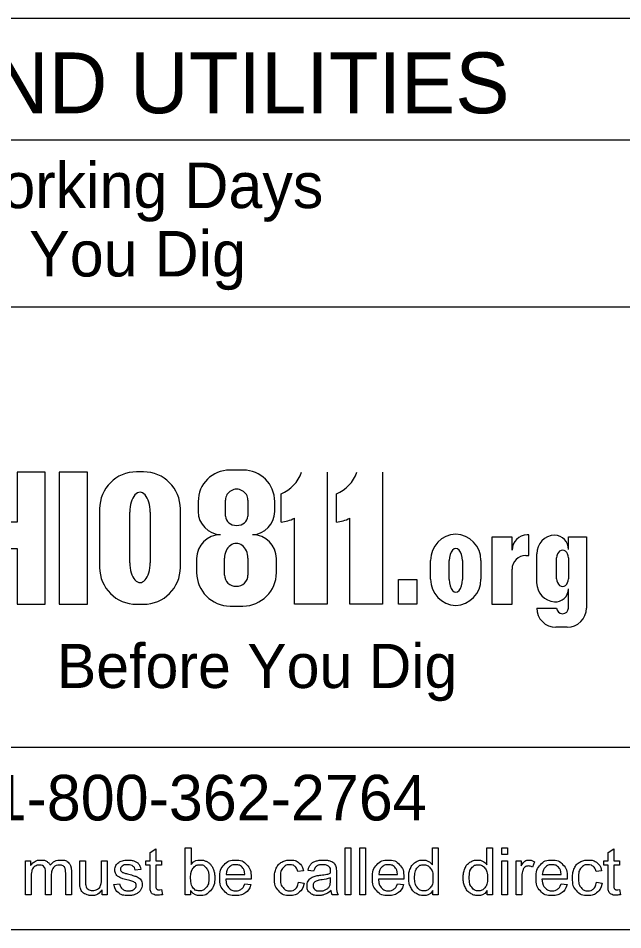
# Model space of a CAD drawing. Extents: x 0 to 34, y 0 to 22.
# Drawn here: x 5.246 to 7.234, y 2.235 to 5.235 of the extents above; entities that cross this region are included whole.
import ezdxf

# ---------------------------------------------------------------- set-up
doc = ezdxf.new("R2010")
doc.units = 0
doc.layers.add('SH_Data', color=7, linetype='Continuous')

msp = doc.modelspace()

# ---------------------------------------------------------------- linework, layer by layer
at = {"layer": 'SH_Data'}
for p, q in [((3.2423, 5.2348), (7.9923, 5.2348)), ((3.2423, 4.8348), (7.9923, 4.8348)), ((3.2423, 4.2848), (7.9923, 4.2848)), ((5.6572, 3.7418), (5.6347, 3.7418)), ((5.9855, 3.7477), (5.941, 3.7477)), ((6.2616, 3.7405), (6.2616, 3.3059)), ((6.4435, 3.7405), (6.4435, 3.3059)), ((6.11, 3.5766), (6.11, 3.6691)), ((6.292, 3.5766), (6.292, 3.6691)), ((5.8374, 3.6441), (5.8374, 3.6111)), ((5.9273, 3.5957), (5.9273, 3.649)), ((6.0008, 3.649), (6.0008, 3.5957)), ((6.0891, 3.6111), (6.0891, 3.6441)), ((5.5132, 3.6203), (5.5132, 3.4274)), ((5.6122, 3.4429), (5.6122, 3.6091)), ((5.6799, 3.6091), (5.6799, 3.4429)), ((5.7787, 3.4274), (5.7787, 3.6203)), ((6.1539, 3.3059), (6.1539, 3.5893)), ((6.3359, 3.3059), (6.3359, 3.5893)), ((6.8696, 3.5273), (6.8033, 3.5273)), ((6.8033, 3.5273), (6.8033, 3.3059)), ((6.8696, 3.4844), (6.8696, 3.5273)), ((6.9249, 3.5343), (6.9195, 3.5343)), ((6.9249, 3.4665), (6.9249, 3.5343)), ((7.055, 3.4864), (7.055, 3.5285)), ((7.055, 3.5285), (7.1142, 3.5285)), ((7.1142, 3.5285), (7.1142, 3.2937)), ((5.8324, 3.4565), (5.8324, 3.4102)), ((5.924, 3.4022), (5.924, 3.4577)), ((6.0012, 3.4577), (6.0012, 3.4022)), ((6.0946, 3.4102), (6.0946, 3.4565)), ((6.6015, 3.3886), (6.6015, 3.4502)), ((6.6626, 3.3875), (6.6626, 3.4502)), ((6.7063, 3.4502), (6.7063, 3.3875)), ((6.7674, 3.4502), (6.7674, 3.3886)), ((6.9144, 3.4665), (6.9249, 3.4665)), ((6.9506, 3.3771), (6.9506, 3.4717)), ((7.0162, 3.3898), (7.0162, 3.4591)), ((7.055, 3.4591), (7.055, 3.3898)), ((6.8696, 3.3059), (6.8696, 3.4217)), ((7.055, 3.2937), (7.055, 3.3567)), ((5.6347, 3.3059), (5.6572, 3.3059)), ((5.9423, 3.3003), (5.9847, 3.3003)), ((6.2616, 3.3059), (6.1539, 3.3059)), ((6.4435, 3.3059), (6.3359, 3.3059)), ((6.8033, 3.3059), (6.8696, 3.3059)), ((6.9506, 3.2937), (7.0162, 3.2937)), ((7.0507, 3.2302), (7.0141, 3.2302)), ((7.9923, 2.8348), (3.2423, 2.8348)), ((7.9923, 2.2348), (3.2423, 2.2348))]:
    msp.add_line(p, q, dxfattribs=at)
for points in [[(5.1728, 3.4897), (5.242, 3.4897), (5.242, 3.3059), (5.3343, 3.3059), (5.3343, 3.7405), (5.242, 3.7405), (5.242, 3.5766), (5.1728, 3.5766), (5.1728, 3.7405)], [(5.3804, 3.3059), (5.4738, 3.3059), (5.4738, 3.7405), (5.3804, 3.7405), (5.3804, 3.3059)], [(5.911, 3.5351), (5.911, 3.5351)], [(6.016, 3.5351), (6.016, 3.5351)], [(5.6791, 2.3828), (5.6791, 2.4471), (5.6651, 2.4471), (5.6651, 2.4618), (5.6791, 2.4618), (5.6791, 2.4894), (5.698, 2.5007), (5.698, 2.4618), (5.7169, 2.4618), (5.7169, 2.4471), (5.698, 2.4471), (5.698, 2.3817)], [(5.8125, 2.3501), (5.795, 2.3501), (5.795, 2.5041), (5.8139, 2.5041), (5.8139, 2.4493)], [(6.3209, 2.3501), (6.3209, 2.5041), (6.3398, 2.5041), (6.3398, 2.3501), (6.3209, 2.3501)], [(6.3687, 2.3501), (6.3687, 2.5041), (6.3876, 2.5041), (6.3876, 2.3501), (6.3687, 2.3501)], [(6.6075, 2.4489), (6.6075, 2.5041), (6.6264, 2.5041), (6.6264, 2.3501), (6.6089, 2.3501)], [(6.7869, 2.4489), (6.7869, 2.5041), (6.8058, 2.5041), (6.8058, 2.3501), (6.7883, 2.3501)], [(6.8356, 2.4824), (6.8356, 2.5041), (6.8545, 2.5041), (6.8545, 2.4824), (6.8356, 2.4824)], [(7.1855, 2.3828), (7.1855, 2.4471), (7.1715, 2.4471), (7.1715, 2.4618), (7.1855, 2.4618), (7.1855, 2.4894), (7.2044, 2.5007), (7.2044, 2.4618), (7.2233, 2.4618), (7.2233, 2.4471), (7.2044, 2.4471), (7.2044, 2.3817)], [(5.2692, 2.3501), (5.2692, 2.4618), (5.2861, 2.4618), (5.2861, 2.446)], [(5.4479, 2.3926), (5.4479, 2.4618), (5.4668, 2.4618), (5.4668, 2.3999)], [(5.5194, 2.402), (5.5194, 2.4618), (5.5383, 2.4618), (5.5383, 2.3501), (5.5214, 2.3501)], [(6.8356, 2.3501), (6.8356, 2.4618), (6.8545, 2.4618), (6.8545, 2.3501), (6.8356, 2.3501)], [(6.883, 2.3501), (6.883, 2.4618), (6.9, 2.4618), (6.9, 2.4449)], [(5.649, 2.4329), (5.6305, 2.4304)], [(6.9436, 2.4582), (6.9369, 2.4407)], [(5.2881, 2.408), (5.2881, 2.3501), (5.2692, 2.3501)], [(5.3544, 2.4149), (5.3544, 2.3501), (5.3355, 2.3501), (5.3355, 2.4226)], [(5.4205, 2.4267), (5.4205, 2.3501), (5.4016, 2.3501), (5.4016, 2.4204)], [(6.0111, 2.4011), (5.9279, 2.4011)], [(5.929, 2.4166), (5.9913, 2.4166)], [(6.1838, 2.4289), (6.1654, 2.4261)], [(6.2171, 2.4274), (6.1986, 2.4298)], [(6.2729, 2.3992), (6.273, 2.4061)], [(6.292, 2.4221), (6.292, 2.3969)], [(6.5133, 2.4011), (6.43, 2.4011)], [(6.4311, 2.4166), (6.4934, 2.4166)], [(6.9019, 2.4086), (6.9019, 2.3501), (6.883, 2.3501)], [(7.0512, 2.4011), (6.968, 2.4011)], [(6.969, 2.4166), (7.0314, 2.4166)], [(7.1641, 2.4289), (7.1457, 2.4261)], [(5.5604, 2.3835), (5.5791, 2.3864)], [(5.9911, 2.3862), (6.0106, 2.3837)], [(6.167, 2.391), (6.1855, 2.3885)], [(6.4932, 2.3862), (6.5127, 2.3837)], [(7.0312, 2.3862), (7.0507, 2.3837)], [(7.1473, 2.391), (7.1659, 2.3885)], [(5.5214, 2.3501), (5.5214, 2.3666)], [(5.7169, 2.367), (5.7196, 2.3503)], [(5.8125, 2.3641), (5.8125, 2.3501)], [(6.298, 2.3501), (6.2783, 2.3501)], [(6.6089, 2.3501), (6.6089, 2.3642)], [(6.7883, 2.3501), (6.7883, 2.3642)], [(7.2233, 2.367), (7.226, 2.3503)]]:
    msp.add_lwpolyline(points, dxfattribs=at)
msp.add_lwpolyline([(6.4963, 3.3875), (6.5562, 3.3875), (6.5562, 3.3059), (6.4963, 3.3059)], close=True, dxfattribs=at)
for centre, radius, start, end in [((5.6347, 3.6203), 0.1215, 90, 180), ((5.6572, 3.6203), 0.1215, 0, 90), ((5.941, 3.6441), 0.1036, 90, 180), ((5.9855, 3.6441), 0.1036, 0, 90), ((6.064, 3.7801), 0.1202, 292.5572, 340.7355), ((6.2459, 3.7801), 0.1202, 292.5572, 340.7355), ((5.9135, 3.6111), 0.076, 180, 268.1442), ((6.0131, 3.6111), 0.076, 272.2058, 0), ((6.0992, 3.6962), 0.1202, 275.1733, 297.0931), ((6.2811, 3.6962), 0.1202, 275.1733, 297.0931), ((5.911, 3.4565), 0.0786, 90, 180), ((6.016, 3.4565), 0.0786, 0, 90), ((6.6884, 3.4502), 0.0869, 92.5886, 180), ((6.6805, 3.4502), 0.0869, 0, 87.4114), ((6.9195, 3.4844), 0.0498, 90, 180), ((7.0129, 3.4717), 0.0623, 92.6865, 180), ((7.0074, 3.4864), 0.0476, 0, 86.9262), ((6.9144, 3.4217), 0.0448, 90, 180), ((5.6347, 3.4274), 0.1215, 180, 270), ((5.6572, 3.4274), 0.1215, 270, 0), ((5.9423, 3.4102), 0.1099, 180, 270), ((5.9847, 3.4102), 0.1099, 270, 0), ((6.6884, 3.3886), 0.0869, 180, 267.4114), ((6.6805, 3.3886), 0.0869, 272.5886, 0), ((7.0134, 3.3771), 0.0629, 180, 265.7132), ((7.0126, 3.3567), 0.0424, 264.7825, 0), ((7.0141, 3.2937), 0.0635, 180, 270), ((7.0507, 3.2937), 0.0635, 270, 0)]:
    msp.add_arc(centre, radius, start, end, dxfattribs=at)
for centre, major_axis, ratio, start_param, end_param in [((5.6461, 3.6091), (0, 0.0657), 0.514403, 4.712389, 7.853982), ((5.964, 3.649), (0.0368, 0), 0.969373, 0, 3.141593), ((5.964, 3.5957), (0.0368, 0), 0.818453, 3.141593, 6.283185), ((5.9626, 3.4577), (0, 0.0486), 0.794529, 4.712389, 7.853982), ((6.6845, 3.4502), (0, 0.0395), 0.553236, 4.712389, 7.853982), ((7.0356, 3.4591), (0, 0.025), 0.777179, 4.712389, 7.853982), ((5.6461, 3.4429), (0, 0.0657), 0.514403, 1.570796, 4.712389), ((5.9626, 3.4022), (0.0386, 0), 0.959837, 3.141593, 6.283185), ((6.6845, 3.3875), (0, 0.0419), 0.522014, 1.570796, 4.712389), ((7.0356, 3.3898), (0, 0.025), 0.777179, 1.570796, 4.712389), ((7.0356, 3.2937), (0.0194, 0), 0.959012, 3.141593, 6.283185)]:
    msp.add_ellipse(centre, major_axis=major_axis, ratio=ratio, start_param=start_param, end_param=end_param, dxfattribs=at)
for points, degree in [([(5.2861, 2.446), (5.2913, 2.4542), (5.3, 2.4592), (5.3088, 2.4642), (5.3199, 2.4642), (5.3323, 2.4642), (5.3402, 2.4591), (5.3482, 2.4539), (5.3514, 2.4446), (5.3647, 2.4642), (5.3859, 2.4642), (5.4026, 2.4642), (5.4115, 2.455), (5.4205, 2.4458), (5.4205, 2.4267)], 3), ([(5.5791, 2.3864), (5.5806, 2.3752), (5.5879, 2.3692), (5.5951, 2.3632), (5.608, 2.3632), (5.6211, 2.3632), (5.6274, 2.3685), (5.6337, 2.3738), (5.6337, 2.381), (5.6337, 2.3874), (5.6282, 2.3911), (5.6243, 2.3936), (5.6088, 2.3975), (5.588, 2.4027), (5.5799, 2.4066), (5.5719, 2.4104), (5.5677, 2.4172), (5.5636, 2.4239), (5.5636, 2.4321), (5.5636, 2.4396), (5.567, 2.4459), (5.5704, 2.4523), (5.5763, 2.4565), (5.5807, 2.4597), (5.5883, 2.462), (5.596, 2.4642), (5.6047, 2.4642), (5.6179, 2.4642), (5.6278, 2.4604), (5.6377, 2.4567), (5.6425, 2.4502), (5.6472, 2.4437), (5.649, 2.4329)], 3), ([(5.8139, 2.4493), (5.8259, 2.4642), (5.8445, 2.4642), (5.8548, 2.4642), (5.864, 2.4601), (5.8732, 2.4559), (5.8791, 2.4484), (5.885, 2.4409), (5.8884, 2.4303), (5.8917, 2.4197), (5.8917, 2.4076), (5.8917, 2.379), (5.8776, 2.3633), (5.8634, 2.3477), (5.8435, 2.3477), (5.8238, 2.3477), (5.8125, 2.3641)], 3), ([(6.0106, 2.3837), (6.006, 2.3666), (5.9935, 2.3571), (5.981, 2.3477), (5.9616, 2.3477), (5.9371, 2.3477), (5.9228, 2.3627), (5.9084, 2.3778), (5.9084, 2.405), (5.9084, 2.4332), (5.9229, 2.4487), (5.9374, 2.4642), (5.9605, 2.4642), (5.9829, 2.4642), (5.9971, 2.449), (6.0112, 2.4338), (6.0112, 2.4061), (6.0112, 2.4044), (6.0111, 2.4011)], 3), ([(6.1855, 2.3885), (6.1825, 2.3694), (6.1699, 2.3585), (6.1574, 2.3477), (6.1391, 2.3477), (6.1162, 2.3477), (6.1023, 2.3626), (6.0884, 2.3776), (6.0884, 2.4055), (6.0884, 2.4236), (6.0943, 2.4371), (6.1003, 2.4507), (6.1126, 2.4575), (6.1248, 2.4642), (6.1392, 2.4642), (6.1574, 2.4642), (6.169, 2.455), (6.1805, 2.4458), (6.1838, 2.4289)], 3), ([(6.1986, 2.4298), (6.2011, 2.4417), (6.2069, 2.449), (6.2126, 2.4563), (6.2236, 2.4603), (6.2345, 2.4642), (6.2489, 2.4642), (6.2631, 2.4642), (6.2721, 2.4609), (6.281, 2.4575), (6.2852, 2.4524), (6.2894, 2.4473), (6.2911, 2.4395), (6.292, 2.4347), (6.292, 2.4221)], 3), ([(6.5127, 2.3837), (6.5081, 2.3666), (6.4956, 2.3571), (6.4831, 2.3477), (6.4637, 2.3477), (6.4392, 2.3477), (6.4249, 2.3627), (6.4106, 2.3778), (6.4106, 2.405), (6.4106, 2.4332), (6.4251, 2.4487), (6.4395, 2.4642), (6.4627, 2.4642), (6.485, 2.4642), (6.4992, 2.449), (6.5134, 2.4338), (6.5134, 2.4061), (6.5134, 2.4044), (6.5133, 2.4011)], 3), ([(6.6089, 2.3642), (6.5983, 2.3477), (6.5777, 2.3477), (6.5644, 2.3477), (6.5532, 2.355), (6.542, 2.3624), (6.5358, 2.3756), (6.5297, 2.3887), (6.5297, 2.4058), (6.5297, 2.4225), (6.5353, 2.4361), (6.5408, 2.4497), (6.5519, 2.457), (6.563, 2.4642), (6.5768, 2.4642), (6.5869, 2.4642), (6.5947, 2.46), (6.6026, 2.4557), (6.6075, 2.4489)], 3), ([(6.7883, 2.3642), (6.7777, 2.3477), (6.7571, 2.3477), (6.7437, 2.3477), (6.7325, 2.355), (6.7213, 2.3624), (6.7152, 2.3756), (6.709, 2.3887), (6.709, 2.4058), (6.709, 2.4225), (6.7146, 2.4361), (6.7202, 2.4497), (6.7313, 2.457), (6.7424, 2.4642), (6.7561, 2.4642), (6.7662, 2.4642), (6.7741, 2.46), (6.7819, 2.4557), (6.7869, 2.4489)], 3), ([(6.9, 2.4449), (6.9065, 2.4567), (6.912, 2.4605), (6.9175, 2.4642), (6.9242, 2.4642), (6.9337, 2.4642), (6.9436, 2.4582)], 3), ([(7.0507, 2.3837), (7.0461, 2.3666), (7.0336, 2.3571), (7.0211, 2.3477), (7.0016, 2.3477), (6.9772, 2.3477), (6.9628, 2.3627), (6.9485, 2.3778), (6.9485, 2.405), (6.9485, 2.4332), (6.963, 2.4487), (6.9775, 2.4642), (7.0006, 2.4642), (7.023, 2.4642), (7.0371, 2.449), (7.0513, 2.4338), (7.0513, 2.4061), (7.0513, 2.4044), (7.0512, 2.4011)], 3), ([(7.1659, 2.3885), (7.1628, 2.3694), (7.1503, 2.3585), (7.1377, 2.3477), (7.1194, 2.3477), (7.0965, 2.3477), (7.0826, 2.3626), (7.0687, 2.3776), (7.0687, 2.4055), (7.0687, 2.4236), (7.0747, 2.4371), (7.0807, 2.4507), (7.0929, 2.4575), (7.1052, 2.4642), (7.1196, 2.4642), (7.1377, 2.4642), (7.1493, 2.455), (7.1609, 2.4458), (7.1641, 2.4289)], 3), ([(5.3355, 2.4226), (5.3355, 2.4352), (5.3308, 2.4415), (5.3262, 2.4478), (5.3157, 2.4478), (5.3077, 2.4478), (5.3009, 2.4436), (5.2941, 2.4394), (5.2911, 2.4313), (5.2881, 2.4232), (5.2881, 2.408)], 3), ([(5.4016, 2.4204), (5.4016, 2.4317), (5.3997, 2.4367), (5.3979, 2.4417), (5.393, 2.4448), (5.3882, 2.4478), (5.3817, 2.4478), (5.3699, 2.4478), (5.3621, 2.44), (5.3544, 2.4322), (5.3544, 2.4149)], 3), ([(5.6305, 2.4304), (5.6292, 2.4391), (5.6232, 2.4439), (5.6171, 2.4487), (5.6061, 2.4487), (5.593, 2.4487), (5.5874, 2.4444), (5.5819, 2.4401), (5.5819, 2.4343), (5.5819, 2.4306), (5.5842, 2.4277), (5.5865, 2.4246), (5.5914, 2.4226), (5.5943, 2.4216), (5.6082, 2.4178), (5.6283, 2.4124), (5.6362, 2.409), (5.6442, 2.4056), (5.6487, 2.3991), (5.6532, 2.3926), (5.6532, 2.3829), (5.6532, 2.3735), (5.6477, 2.3652), (5.6422, 2.3568), (5.6318, 2.3522), (5.6213, 2.3477), (5.6082, 2.3477), (5.5864, 2.3477), (5.575, 2.3567), (5.5635, 2.3657), (5.5604, 2.3835)], 3), ([(5.8123, 2.4068), (5.8123, 2.3867), (5.8177, 2.3778), (5.8266, 2.3632), (5.8419, 2.3632), (5.8542, 2.3632), (5.8632, 2.3739), (5.8723, 2.3847), (5.8723, 2.4061), (5.8723, 2.4279), (5.8636, 2.4383), (5.855, 2.4487), (5.8427, 2.4487), (5.8303, 2.4487), (5.8213, 2.438), (5.8123, 2.4272), (5.8123, 2.4068)], 3), ([(5.9913, 2.4166), (5.99, 2.4307), (5.9841, 2.4378), (5.9751, 2.4487), (5.9607, 2.4487), (5.9477, 2.4487), (5.9388, 2.44), (5.9299, 2.4312), (5.929, 2.4166)], 3), ([(6.1654, 2.4261), (6.1627, 2.4374), (6.1561, 2.443), (6.1494, 2.4487), (6.14, 2.4487), (6.1257, 2.4487), (6.1168, 2.4385), (6.1078, 2.4282), (6.1078, 2.4061), (6.1078, 2.3836), (6.1165, 2.3734), (6.1251, 2.3632), (6.1389, 2.3632), (6.1501, 2.3632), (6.1575, 2.37), (6.165, 2.3768), (6.167, 2.391)], 3), ([(6.2745, 2.3639), (6.264, 2.355), (6.2543, 2.3513), (6.2445, 2.3477), (6.2334, 2.3477), (6.215, 2.3477), (6.2052, 2.3566), (6.1953, 2.3656), (6.1953, 2.3796), (6.1953, 2.3878), (6.199, 2.3945), (6.2027, 2.4013), (6.2088, 2.4054), (6.2148, 2.4095), (6.2224, 2.4116), (6.2279, 2.4131), (6.2392, 2.4144), (6.2621, 2.4171), (6.2729, 2.4209), (6.273, 2.4248), (6.273, 2.4259), (6.273, 2.4375), (6.2676, 2.4422), (6.2604, 2.4486), (6.2462, 2.4486), (6.2328, 2.4486), (6.2265, 2.4439), (6.2202, 2.4393), (6.2171, 2.4274)], 3), ([(6.4934, 2.4166), (6.4922, 2.4307), (6.4863, 2.4378), (6.4772, 2.4487), (6.4628, 2.4487), (6.4498, 2.4487), (6.4409, 2.44), (6.432, 2.4312), (6.4311, 2.4166)], 3), ([(6.5492, 2.4058), (6.5492, 2.3844), (6.5582, 2.3738), (6.5673, 2.3632), (6.5795, 2.3632), (6.5919, 2.3632), (6.6006, 2.3733), (6.6093, 2.3835), (6.6093, 2.4043), (6.6093, 2.4272), (6.6005, 2.4379), (6.5916, 2.4486), (6.5787, 2.4486), (6.5661, 2.4486), (6.5576, 2.4383), (6.5492, 2.428), (6.5492, 2.4058)], 3), ([(6.7285, 2.4058), (6.7285, 2.3844), (6.7376, 2.3738), (6.7466, 2.3632), (6.7589, 2.3632), (6.7713, 2.3632), (6.78, 2.3733), (6.7886, 2.3835), (6.7886, 2.4043), (6.7886, 2.4272), (6.7798, 2.4379), (6.771, 2.4486), (6.7581, 2.4486), (6.7454, 2.4486), (6.737, 2.4383), (6.7285, 2.428), (6.7285, 2.4058)], 3), ([(6.9369, 2.4407), (6.93, 2.4447), (6.9231, 2.4447), (6.917, 2.4447), (6.9121, 2.441), (6.9072, 2.4373), (6.9051, 2.4307), (6.9019, 2.4206), (6.9019, 2.4086)], 3), ([(7.0314, 2.4166), (7.0301, 2.4307), (7.0242, 2.4378), (7.0152, 2.4487), (7.0008, 2.4487), (6.9878, 2.4487), (6.9789, 2.44), (6.97, 2.4312), (6.969, 2.4166)], 3), ([(7.1457, 2.4261), (7.1431, 2.4374), (7.1364, 2.443), (7.1297, 2.4487), (7.1203, 2.4487), (7.106, 2.4487), (7.0971, 2.4385), (7.0882, 2.4282), (7.0882, 2.4061), (7.0882, 2.3836), (7.0968, 2.3734), (7.1054, 2.3632), (7.1193, 2.3632), (7.1304, 2.3632), (7.1379, 2.37), (7.1453, 2.3768), (7.1473, 2.391)], 3), ([(5.4668, 2.3999), (5.4668, 2.3851), (5.468, 2.38), (5.4698, 2.3725), (5.4755, 2.3682), (5.4813, 2.364), (5.4898, 2.364), (5.4983, 2.364), (5.5058, 2.3684), (5.5132, 2.3727), (5.5163, 2.3802), (5.5194, 2.3877), (5.5194, 2.402)], 3), ([(5.9279, 2.4011), (5.9289, 2.3827), (5.9383, 2.3729), (5.9477, 2.3632), (5.9616, 2.3632), (5.972, 2.3632), (5.9794, 2.3687), (5.9868, 2.3741), (5.9911, 2.3862)], 3), ([(6.273, 2.4061), (6.2627, 2.4019), (6.2421, 2.399), (6.2304, 2.3973), (6.2256, 2.3952), (6.2207, 2.3931), (6.2181, 2.3891), (6.2155, 2.385), (6.2155, 2.3801), (6.2155, 2.3725), (6.2212, 2.3675), (6.2269, 2.3625), (6.2379, 2.3625), (6.2489, 2.3625), (6.2574, 2.3672), (6.2659, 2.372), (6.2698, 2.3803), (6.2729, 2.3867), (6.2729, 2.3992)], 3), ([(6.43, 2.4011), (6.4311, 2.3827), (6.4404, 2.3729), (6.4498, 2.3632), (6.4638, 2.3632), (6.4742, 2.3632), (6.4815, 2.3687), (6.4889, 2.3741), (6.4932, 2.3862)], 3), ([(6.968, 2.4011), (6.969, 2.3827), (6.9784, 2.3729), (6.9877, 2.3632), (7.0017, 2.3632), (7.0121, 2.3632), (7.0195, 2.3687), (7.0268, 2.3741), (7.0312, 2.3862)], 3), ([(5.5214, 2.3666), (5.5084, 2.3477), (5.486, 2.3477), (5.4762, 2.3477), (5.4676, 2.3515), (5.4591, 2.3552), (5.4549, 2.361), (5.4508, 2.3667), (5.4491, 2.375), (5.4479, 2.3806), (5.4479, 2.3926)], 3), ([(5.7196, 2.3503), (5.7116, 2.3486), (5.7053, 2.3486), (5.695, 2.3486), (5.6893, 2.3519), (5.6837, 2.3551), (5.6814, 2.3605), (5.6791, 2.3658), (5.6791, 2.3828)], 3), ([(5.698, 2.3817), (5.698, 2.3736), (5.6989, 2.3713), (5.6999, 2.369), (5.7022, 2.3676), (5.7044, 2.3662), (5.7086, 2.3662), (5.7117, 2.3662), (5.7169, 2.367)], 3), ([(6.292, 2.3969), (6.292, 2.3706), (6.2932, 2.3636), (6.2944, 2.3566), (6.298, 2.3501)], 3), ([(7.226, 2.3503), (7.218, 2.3486), (7.2117, 2.3486), (7.2014, 2.3486), (7.1958, 2.3519), (7.1901, 2.3551), (7.1878, 2.3605), (7.1855, 2.3658), (7.1855, 2.3828)], 3), ([(7.2044, 2.3817), (7.2044, 2.3736), (7.2054, 2.3713), (7.2064, 2.369), (7.2086, 2.3676), (7.2109, 2.3662), (7.215, 2.3662), (7.2182, 2.3662), (7.2233, 2.367)], 3), ([(6.2783, 2.3501), (6.2754, 2.356), (6.2745, 2.3639)], 2)]:
    msp.add_open_spline(points, degree=degree, dxfattribs=at)

# ---------------------------------------------------------------- texts
for s, height, p in [('UNDERGROUND UTILITIES', 0.2, (3.3992, 4.9221)), ('Contact Two Working Days', 0.15, (3.819, 4.6099)), ('Before You Dig', 0.15, (4.6346, 4.3849)), ('Before You Dig', 0.1452, (5.3727, 3.0305)), ('OHIO811, 8-1-1, or 1-800-362-2764', 0.15, (3.3887, 2.5946))]:
    msp.add_text(s, height=height, dxfattribs=at).set_placement(p)

doc.saveas('drawing.dxf')
